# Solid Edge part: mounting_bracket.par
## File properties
Title: Mounting Bracket
Author: Lee Sichello
Template: Metric Part.par
Last saved by: Lee
Revision: 7
Application: Solid Edge
Material: Aluminum
Face Style: Model Default
Coef. of Thermal Exp: 0.0
Thermal Conductivity: 0.0
Specific Heat: 0.0
Modulus of Elasticity: 0.0
Poisson's Ratio: 0.0
Yield Stress: 0.0
Ultimate Stress: 0.0
Elongation: 0.0
Manager: Garth Huber
Company: U of R Physics
Accuracy: 0.990
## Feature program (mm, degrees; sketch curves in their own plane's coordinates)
sketch for "unnamed Protrusion 1" plane through (0, 0, 0) normal (0, -1, 0) x-axis (1, 0, 0)
  line (-76.2, 50.8) -> (-76.2, -101.6)
  line (-76.2, -101.6) -> (76.2, -101.6)
  line (76.2, -101.6) -> (76.2, 50.8)
  line (-76.2, 50.8) -> (76.2, 50.8)
extrude "unnamed Protrusion 1" add finite 38.1 symmetric
sketch for "ExtrudedCutout_1" plane through (0, 0, 0) normal (1, 0, 0) x-axis (0, 1, 0)
  circle centre (-590.55, 646.2) radius 875.4
extrude "ExtrudedCutout_1" cut finite 152.4 symmetric
fillet "Round_1" radius 12.7
fillet "Round_2" radius 5
sketch for "Hole_1" plane through (0, -19.05, -56.7543) normal (0, -1, 0) x-axis (1, 0, 0)
  hole centre (0, 2.7543) bore radius 12.7
hole "Hole_1" diameter 25.4 through
fillet "Round_3" radius 2.5
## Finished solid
Body 1: solid body, 21 faces, 44 edges, 24 vertices.
  Faces by surface: cylinder 10, torus 6, plane 5
  Edges by curve: circle 22, line 18, intersection 4
Bounding box of the edges (mm; curved faces can reach further): 152.400 x 38.100 x 119.538, from (-76.2, -19.05, -101.6) to (76.2, 19.05, 17.9381).
Cylindrical faces by radius (mm): R5 x6, R12.7 x3, R875.4 x1
Toroidal faces (ring radius, tube radius in mm): R7.7 r5 x4, R15.2 r2.5 x2
Planar faces by outward normal: +x 1, +y 1, -x 1, -y 1, -z 1
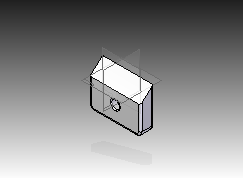
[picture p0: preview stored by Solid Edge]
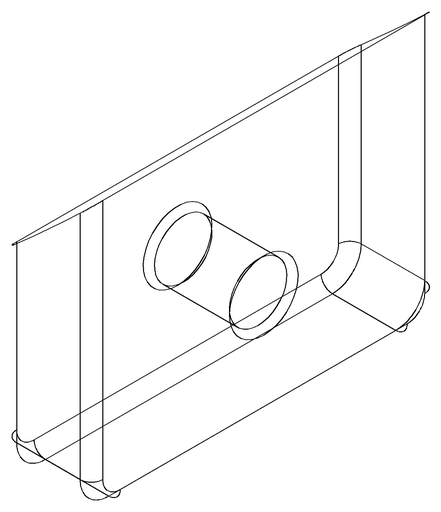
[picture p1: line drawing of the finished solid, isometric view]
